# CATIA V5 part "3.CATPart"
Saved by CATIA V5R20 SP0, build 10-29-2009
Part number: 3
Bounding box of the stored display mesh (mm): x -76.273 to 76.273, y -0.613 to 290.985, z -5.791 to 79.225
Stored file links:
  E:\Ehsan\Amoozesh\CATIA\CATIA Course\Advanced\Videos\Session-23\3.CATPart
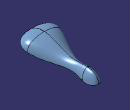
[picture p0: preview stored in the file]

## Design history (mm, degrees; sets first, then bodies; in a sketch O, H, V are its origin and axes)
AxisSystem1: origin (0, 0, 0), X (1, 0, 0), Y (0, 1, 0), Z (0, 0, 1)
Set1
  Combine1: Curve1 Sketch3, Curve2 Sketch5
  Symmetry1: ToTransfor Combine1, Reference YZ plane of AxisSystem1
  Plane1: type Offset, RefPlane ZX plane of AxisSystem1, Offset 55
  Plane2: type Offset, RefPlane ZX plane of AxisSystem1, Offset 240
  Sketch1 on Plane2, origin (0, 240, 0), H (-1, 0, 0), V (0, 0, 1)
    reference intersected point E1 (19.5887, -3.0694) from edge of Combine1
    reference intersected point E2 (-19.5887, -3.0694) from edge of Symmetry1
    reference intersected point E3 (0, 38.636) from Sketch4.S1
    spline S1 through (-19.5887, -3.0694) (0, 38.636) (19.5887, -3.0694)
    point P1 (-19.5887, -3.0694)
    point P2 (0, 38.636)
    point P3 (19.5887, -3.0694)
    coincidence: P1 E2, P2 E3, P3 E1
  Sketch2 on Plane1, origin (0, 55, 0), H (-1, 0, 0), V (0, 0, 1)
    reference intersected point E1 (72.905, 37.2977) from edge of Combine1
    reference intersected point E2 (-72.905, 37.2977) from edge of Symmetry1
    reference intersected point E3 (0, 77.9737) from Sketch4.S1
    spline S1 through (-72.905, 37.2977) (0, 77.9737) (72.905, 37.2977)
    point P1 (-72.905, 37.2977)
    point P2 (0, 77.9737)
    point P3 (72.905, 37.2977)
    coincidence: P1 E2, P2 E3, P3 E1
  Split1: ToCut Combine1, Cutting Plane2
  Split2: ToCut Split1, Cutting Plane1
  Split3: ToCut Symmetry1, Cutting Sketch1
  Split4: ToCut Split3, Cutting Plane1
  Loft1: Sections (Sketch2; Sketch1), Guides (Split4; Sketch4; Split2)
  Join1: Elements ({split ToCut Combine1, Cutting Plane2}; {split ToCut Symmetry1, Cutting Sketch1})
  Loft2: Sections (Join1; Sketch1), EndSectionTangent Loft1, Guides Sketch4
  Join2: Elements ({split ToCut Split3, Cutting Plane1}; {split ToCut Split1, Cutting Plane1})
  Loft3: Sections (Join2; Sketch2), EndSectionTangent Loft1, Guides Sketch4
  Join3: Elements (Loft3; Loft1; Loft2)
  ThickSurface1: Surface Join3, TopOffset 1, BotOffset 0
Body1 (main body)
  Sketch3 on XY plane of AxisSystem1, origin (0, 0, 0), H (0, 1, 0), V (-1, 0, 0)
    spline S1 through (0, 0) (34, 75) (84, 62) (250, 20) (275, 16) (290, 0)
    point P1 (0, 0)
    point P2 (290, 0)
    point P3 (34, 75)
    point P4 (84, 62)
    point P5 (250, 20)
    point P6 (275, 16)
    distance P3 V = 34
    distance P4 V = 84
    distance P5 V = 250
    distance P6 V = 275
    distance P2 V = 290
    distance P3 H = 75
    distance P4 H = 62
    distance P5 H = 20
    distance P6 H = 16
    coincidence: P2 H, P1 O
  Sketch4 on YZ plane of AxisSystem1, origin (0, 0, 0), H (0, 1, 0), V (0, 0, 1)
    spline S1 through (0, 62) (25, 75) (96, 68) (210, 38) (275, 29) (290, 0)
    reference projected point E1 (290, 0) from Sketch3.P2
    point P1 (0, 62)
    point P2 (290, 0)
    point P3 (25, 75)
    point P4 (96, 68)
    point P5 (210, 38)
    point P6 (275, 29)
    distance P1 H = 62
    distance P3 H = 75
    distance P4 H = 68
    distance P5 H = 38
    distance P6 H = 29
    distance P3 V = 25
    distance P4 V = 96
    distance P5 V = 210
    distance P6 V = 275
    coincidence: P1 V, P2 H, P2 E1
  Sketch5 on YZ plane of AxisSystem1, origin (0, 0, 0), H (0, 1, 0), V (0, 0, 1)
    spline S1 through (0, 62) (48, 40) (145, 17) (210, 6) (250, -5) (290, 0)
    reference projected point E1 (290, 0) from Sketch3.P2
    reference projected point E2 (0, 62) from Sketch4.P1
    reference intersected line E3 through (0, 0) direction (0, 1) from ZX plane of AxisSystem1
    reference intersected line E4 through (0, 0) direction (0, 1) from ZX plane of AxisSystem1
    reference intersected line E5 through (0, 0) direction (0, 1) from ZX plane of AxisSystem1
    reference intersected line E6 through (0, 0) direction (0, 1) from ZX plane of AxisSystem1
    reference projected line E7 (290, 0) -> (0, 0) from Sketch3.S1
    reference projected line E8 through (0, 0) direction (1, 0) from edge [YZ plane of AxisSystem1 | XY plane of AxisSystem1]
    reference projected line E9 through (0, 0) direction (1, 0) from edge [YZ plane of AxisSystem1 | XY plane of AxisSystem1]
    reference projected line E10 through (0, 0) direction (1, 0) from edge [YZ plane of AxisSystem1 | XY plane of AxisSystem1]
    point P1 (0, 62)
    point P2 (290, 0)
    point P3 (48, 40)
    point P4 (145, 17)
    point P5 (210, 6)
    point P6 (250, -5)
    distance P3 E3 = 48
    distance P4 E4 = 145
    distance P5 E5 = 210
    distance P6 E6 = 250
    distance P3 E7 = 40
    distance P4 E8 = 17
    distance P5 E9 = 6
    distance P6 E10 = 5
    coincidence: P1 V, P2 E1, E2 P1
